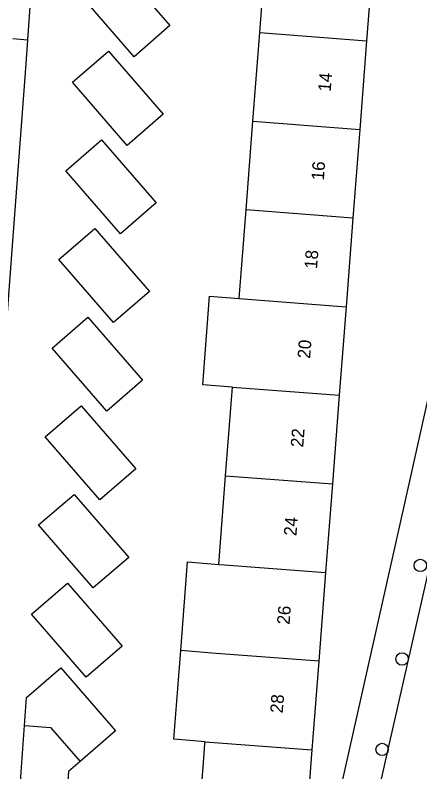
# Model space of a CAD drawing. Extents: x 161845 to 162341, y 381620 to 382158.
# Drawn here: x 161969.2 to 162001.2, y 381790.1 to 381850 of the extents above; entities that cross this region are included whole.
import ezdxf

# ---------------------------------------------------------------- set-up
doc = ezdxf.new("R2010")
doc.units = 0
for name, color, linetype in [('IMGEO_Boom', 7, 'Continuous'), ('IMGEO_Pand', 7, 'Continuous'), ('IMGEO_Pand_nummerreeks', 7, 'Continuous'), ('IMGEO_Rijbaan_lokaal_open', 7, 'Continuous'), ('IMGEO_Voetpad_halfverhard', 7, 'Continuous'), ('IMGEO_Voetpad_open', 7, 'Continuous')]:
    doc.layers.add(name, color=color, linetype=linetype)

msp = doc.modelspace()

# ---------------------------------------------------------------- linework, layer by layer
at = {"layer": 'IMGEO_Boom'}
for centre in [(162001.255, 381806.458), (161999.811, 381799.055), (161998.235, 381791.9)]:
    msp.add_circle(centre, 0.489, dxfattribs=at)
at = {"layer": 'IMGEO_Pand'}
for points in [[(161988.571, 381848.605), (161989.112, 381855.615), (161992.538, 381855.351), (161997.552, 381854.964), (161997.011, 381847.955)], [(161978.64, 381846.696), (161974.315, 381851.686), (161977.149, 381854.142), (161981.474, 381849.152), (161978.64, 381846.696)], [(161988.03, 381841.595), (161988.571, 381848.605)], [(161988.571, 381848.605), (161997.011, 381847.955)], [(161997.011, 381847.955), (161996.47, 381840.945)], [(161980.933, 381842.142), (161978.1, 381839.685), (161973.774, 381844.676), (161976.608, 381847.132), (161980.933, 381842.142)], [(161987.489, 381834.583), (161988.03, 381841.595)], [(161988.03, 381841.595), (161996.47, 381840.945)], [(161996.47, 381840.945), (161995.929, 381833.933)], [(161980.392, 381835.13), (161977.558, 381832.674), (161973.233, 381837.664), (161976.067, 381840.12), (161980.392, 381835.13)], [(161986.949, 381827.572), (161987.489, 381834.583)], [(161995.929, 381833.933), (161987.489, 381834.583)], [(161995.929, 381833.933), (161995.389, 381826.922)], [(161979.853, 381828.118), (161977.019, 381825.662), (161972.694, 381830.652), (161975.528, 381833.108), (161979.853, 381828.118)], [(161986.408, 381820.561), (161984.068, 381820.741), (161984.608, 381827.752), (161986.949, 381827.572)], [(161986.949, 381827.572), (161995.389, 381826.922)], [(161995.389, 381826.922), (161994.848, 381819.911)], [(161979.312, 381821.107), (161976.478, 381818.651), (161972.153, 381823.641), (161974.987, 381826.097), (161979.312, 381821.107)], [(161985.867, 381813.55), (161986.408, 381820.561)], [(161986.408, 381820.561), (161994.848, 381819.911)], [(161994.848, 381819.911), (161994.307, 381812.899)], [(161978.771, 381814.096), (161975.939, 381811.641), (161971.614, 381816.629), (161974.446, 381819.085), (161978.771, 381814.096)], [(161985.326, 381806.539), (161985.867, 381813.55)], [(161985.867, 381813.55), (161994.307, 381812.899)], [(161994.307, 381812.899), (161993.766, 381805.889)], [(161978.229, 381807.086), (161975.402, 381804.689), (161971.077, 381809.679), (161973.906, 381812.074), (161978.229, 381807.086)], [(161982.328, 381799.716), (161982.867, 381806.728), (161985.326, 381806.539)], [(161985.326, 381806.539), (161985.792, 381806.503), (161993.766, 381805.889)], [(161993.766, 381805.889), (161993.225, 381798.877)], [(161977.688, 381800.074), (161974.854, 381797.618), (161970.529, 381802.608), (161973.363, 381805.064), (161977.688, 381800.074)], [(161984.244, 381792.516), (161981.789, 381792.705), (161982.328, 381799.716)], [(161993.225, 381798.877), (161984.785, 381799.527), (161982.328, 381799.716)], [(161993.225, 381798.877), (161992.684, 381791.867)], [(161969.969, 381793.786), (161970.127, 381796.004), (161972.849, 381798.365), (161977.175, 381793.376), (161974.364, 381790.938)], [(161969.419, 381786.055), (161969.969, 381793.786)], [(161969.969, 381793.786), (161972.022, 381793.64), (161974.364, 381790.938)], [(161992.684, 381791.867), (161992.143, 381784.853), (161983.703, 381785.505), (161984.088, 381790.491), (161984.228, 381792.307), (161984.244, 381792.516)], [(161984.244, 381792.516), (161992.684, 381791.867)], [(161974.364, 381790.938), (161973.452, 381790.147), (161973.124, 381785.533)]]:
    msp.add_lwpolyline(points, dxfattribs=at)
at = {"layer": 'IMGEO_Rijbaan_lokaal_open'}
msp.add_lwpolyline([(161997.168, 381785.034), (162010.118, 381842.239), (162017.975, 381876.532)], dxfattribs=at)
at = {"layer": 'IMGEO_Voetpad_halfverhard'}
msp.add_lwpolyline([(161989.645, 381903.259), (161986.432, 381900.785), (161982.8, 381897.739), (161982.465, 381896.672), (161978.76, 381884.865), (161974.911, 381871.274), (161970.994, 381859.267), (161970.22, 381848.039)], dxfattribs=at)
at = {"layer": 'IMGEO_Voetpad_open'}
for points in [[(161993.909, 381784.124), (162000, 381811.259), (162006.057, 381838.422), (162012.585, 381866.816), (162015.506, 381878.919), (162015.663, 381880.219), (162015.619, 381881.528), (162015.122, 381883.128), (162013.985, 381885.418), (162004.242, 381899.525), (162004.132, 381899.684)], [(161970.22, 381848.039), (161970.088, 381846.125), (161969, 381831.764), (161967.896, 381817.185), (161967.827, 381816.258), (161966.128, 381788.286), (161965.392, 381788.344)], [(161969.057, 381848.126), (161970.22, 381848.039)]]:
    msp.add_lwpolyline(points, dxfattribs=at)

# ---------------------------------------------------------------- texts
at = {"layer": 'IMGEO_Pand_nummerreeks'}
for s, rotation, p in [('14', 85.58842, (161994.171, 381843.907)), ('16', 85.58842, (161993.63, 381836.896)), ('18', 85.58842, (161993.09, 381829.888)), ('20', 85.58842, (161992.543, 381822.787)), ('22', 85.58842, (161992.001, 381815.77)), ('24', 85.58844, (161991.46, 381808.762)), ('26', 85.58844, (161990.919, 381801.751)), ('28', 85.58842, (161990.379, 381794.743))]:
    msp.add_text(s, height=1, rotation=rotation, dxfattribs=at).set_placement(p)

doc.saveas('drawing.dxf')
